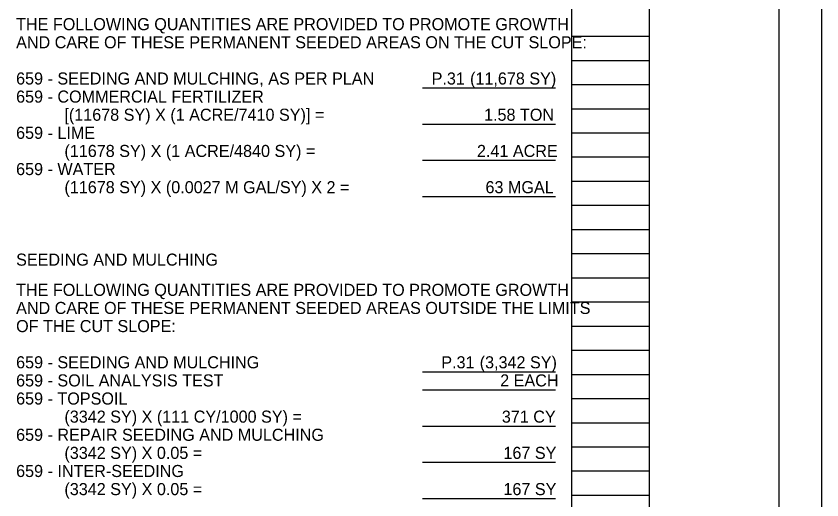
# Model space of a CAD drawing. Extents: x 0 to 34, y 0 to 22.
# Drawn here: x 24.66 to 34, y 5.4 to 11.01 of the extents above; entities that cross this region are included whole.
import ezdxf

# ---------------------------------------------------------------- set-up
doc = ezdxf.new("R2010")
doc.units = 0
for name, color, linetype in [('SH_Border', 7, 'Continuous'), ('SH_Cut_Line', 7, 'Continuous'), ('SH_Data', 7, 'Continuous'), ('SH_Text', 7, 'Continuous'), ('TX_P_Misc', 7, 'Continuous')]:
    doc.layers.add(name, color=color, linetype=linetype)

msp = doc.modelspace()

# ---------------------------------------------------------------- linework, layer by layer
at = {"layer": 'SH_Border'}
msp.add_line((32, 0.5), (32, 21.5), dxfattribs=at)
msp.add_lwpolyline([(1.5, 21.5), (33.5, 21.5), (33.5, 0.5), (1.5, 0.5)], close=True, dxfattribs=at)
at = {"layer": 'SH_Cut_Line'}
msp.add_lwpolyline([(0, 0), (34, 0), (34, 22), (0, 22)], close=True, dxfattribs=at)
at = {"layer": 'SH_Data'}
for p, q in [((31.1, 0.98), (31.1, 21.14)), ((32, 0.98), (32, 21.14)), ((31.1, 10.78), (32, 10.78)), ((31.1, 10.5), (32, 10.5)), ((31.1, 10.22), (32, 10.22)), ((31.1, 9.94), (32, 9.94)), ((31.1, 9.66), (32, 9.66)), ((31.1, 9.38), (32, 9.38)), ((31.1, 9.1), (32, 9.1)), ((31.1, 8.82), (32, 8.82)), ((31.1, 8.54), (32, 8.54)), ((31.1, 8.26), (32, 8.26)), ((31.1, 7.98), (32, 7.98)), ((31.1, 7.7), (32, 7.7)), ((31.1, 7.42), (32, 7.42)), ((31.1, 7.14), (32, 7.14)), ((31.1, 6.86), (32, 6.86)), ((31.1, 6.58), (32, 6.58)), ((31.1, 6.3), (32, 6.3)), ((31.1, 6.02), (32, 6.02)), ((31.1, 5.74), (32, 5.74)), ((31.1, 5.46), (32, 5.46))]:
    msp.add_line(p, q, dxfattribs=at)
at = {"layer": 'TX_P_Misc'}
for p, q in [((29.3724, 10.1812), (30.9131, 10.1812)), ((29.3724, 9.7612), (30.9131, 9.7612)), ((29.3724, 9.3412), (30.9131, 9.3412)), ((29.3724, 8.9212), (30.9131, 8.9212)), ((29.3724, 6.8912), (30.9131, 6.8912)), ((29.3724, 6.6812), (30.9131, 6.6812)), ((29.3724, 6.2612), (30.9131, 6.2612)), ((29.3724, 5.8412), (30.9131, 5.8412)), ((29.3724, 5.4212), (30.9131, 5.4212))]:
    msp.add_line(p, q, dxfattribs=at)

# ---------------------------------------------------------------- texts
at = {"layer": 'SH_Text'}
for s, p in [('THE FOLLOWING QUANTITIES ARE PROVIDED TO PROMOTE GROWTH ', (24.66, 10.85)), ('AND CARE OF THESE PERMANENT SEEDED AREAS ON THE CUT SLOPE:', (24.66, 10.64)), ('659 - SEEDING AND MULCHING, AS PER PLAN', (24.66, 10.22)), ('659 - COMMERCIAL FERTILIZER', (24.66, 10.01)), ('[(11678 SY) X (1 ACRE/7410 SY)] = ', (25.22, 9.8)), ('659 - LIME', (24.66, 9.59)), ('(11678 SY) X (1 ACRE/4840 SY) =', (25.22, 9.38)), ('659 - WATER', (24.66, 9.17)), ('(11678 SY) X (0.0027 M GAL/SY) X 2 =', (25.22, 8.96)), ('SEEDING AND MULCHING', (24.66, 8.12)), ('THE FOLLOWING QUANTITIES ARE PROVIDED TO PROMOTE GROWTH ', (24.66, 7.77)), ('AND CARE OF THESE PERMANENT SEEDED AREAS OUTSIDE THE LIMITS ', (24.66, 7.56)), ('OF THE CUT SLOPE:', (24.66, 7.35)), ('659 - SEEDING AND MULCHING', (24.66, 6.93)), ('659 - SOIL ANALYSIS TEST', (24.66, 6.72)), ('659 - TOPSOIL', (24.66, 6.51)), ('(3342 SY) X (111 CY/1000 SY) =', (25.22, 6.3)), ('659 - REPAIR SEEDING AND MULCHING', (24.66, 6.09)), ('(3342 SY) X 0.05 =', (25.22, 5.88)), ('659 - INTER-SEEDING', (24.66, 5.67)), ('(3342 SY) X 0.05 =', (25.22, 5.46))]:
    msp.add_text(s, height=0.14, dxfattribs=at).set_placement(p)
at = {"layer": 'TX_P_Misc'}
for s, p in [(' (11,678 SY)', (29.8699, 10.22)), ('P.31', (29.4767, 10.22)), ('1.58 TON', (30.0841, 9.8)), ('2.41 ACRE', (30.002, 9.38)), ('63 MGAL', (30.1005, 8.96)), ('P.31', (29.5885, 6.93)), (' (3,342 SY)', (29.9816, 6.93)), ('2 EACH', (30.2711, 6.72)), ('371 CY', (30.2902, 6.3)), ('167 SY', (30.3086, 5.88)), ('167 SY', (30.3086, 5.46))]:
    msp.add_text(s, height=0.14, dxfattribs=at).set_placement(p)

doc.saveas('drawing.dxf')
